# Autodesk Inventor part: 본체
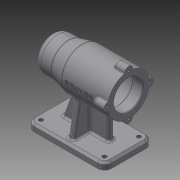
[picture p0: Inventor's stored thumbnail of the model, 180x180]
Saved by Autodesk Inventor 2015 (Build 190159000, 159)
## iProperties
Created: 2019-07
Part Number: 본체
Material: 일반
Document SubType Name: Modeling
Designer: now060
Density: 1 g/cm^3
Appearance: 기본값
Author: now060
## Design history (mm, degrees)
sketch "스케치1"
  geometry: L1 (-56, -35)-(56, -35); L2 (56, -35)-(56, 35); L3 (56, 35)-(-56, 35); L4 (-56, 35)-(-56, -35); L5 (-56, -35)-(56, 35); L6 (56, -35)-(-56, 35); 1 further point
  constraints: 12 end point, 2 midpoint, 2 parallel, 1 horizontal, 1 perpendicular
  dimensions: "d0" = 112 distance of L2.end L3.end; "d1" = 70 distance of L1.end L2.end
extrude "돌출1" new body sketch "스케치1" distance "d2" = 10; taper "d3" = 0 deg
sketch "스케치2"
  geometry: L1 (56, -35)-(56, 35) reference; L2 (-56, 35)-(-56, -35) reference; L3 (-36, 4)-(31, 4); L4 (31, 4)-(31, -4); L5 (31, -4)-(-36, -4); L6 (-36, -4)-(-36, 4); 1 further point
  constraints: 8 end point, 2 parallel, 1 horizontal, 1 perpendicular
  dimensions: "d4" = 25 distance between parallel lines of L1 L4; "d5" = 20 distance between parallel lines of L6 L2; "d6" = 4 distance from line of L3 point (0, 0); "d7" = 8 distance between parallel lines of L5 L3
extrude "돌출2" join sketch "스케치2" distance "d8" = 70; taper "d9" = 0 deg
sketch "스케치3"
  geometry: L1 (56, 35)-(-56, 35) reference; L2 (4, -28)-(-4, -28); L3 (-4, -28)-(-4, 28); L4 (-4, 28)-(4, 28); L5 (4, 28)-(4, -28); L6 (4, -28)-(-4, 28); L7 (-4, -28)-(4, 28); 1 further point
  constraints: 12 end point, 2 midpoint, 2 parallel, 1 horizontal, 1 perpendicular
  dimensions: "d10" = 8 distance between parallel lines of L5 L3; "d11" = 7 distance between parallel lines of L1 L4
extrude "돌출3" join sketch "스케치3" distance "d12" = 70; taper "d13" = 0 deg
feature "면 기울기1" dims angle "d14" = 10 deg
feature "면 기울기2" dims angle "d15" = 20 deg
sketch "스케치4"
  geometry: L1 (-56, 0)-(-56, 10) reference; L2 (-56, 10)-(-31, 10) reference; L3 (-31, 10)-(-31, 80) reference; L4 (-31, 80)-(10.522, 80) reference; L5 (10.522, 80)-(36, 10) reference; L6 (36, 10)-(56, 10) reference; L7 (56, 10)-(56, 0) reference; L8 (56, 0)-(-56, 0) reference; L9 (56, 80)-(-56, 80); L10 (-56, 80)-(-56, 110); L11 (-56, 110)-(11, 110); L12 (11, 110)-(31, 105); L13 (31, 105)-(56, 105); L14 (56, 105)-(56, 80); 1 further point
  constraints: 12 end point, 3 perpendicular, 1 collinear, 1 horizontal, 1 parallel
  dimensions: "d16" = 25 distance of L13.end L9.start; "d17" = 30 vertical distance of L9.start L11.end; "d18" = 25 distance from line of L12.end L14; "d19" = 45 distance from line of L11.end L14; "d20" = 112 distance between parallel lines of L10 L14; "d21" = 0 distance between parallel lines of L1 L10
revolve "회전1" sketch "스케치4" stored, may be unused: angle "d22" = 90 deg
fillet "모깎기1" dims "d23" = 10
sketch "스케치5"
  geometry: C1 r 6 at (-30, 0); 2 further points
  constraints: 2 horizontal alignment, 1 centre point, 1 other
  dimensions: "d24" = 6 radius of C1
extrude "돌출4" join sketch "스케치5" distance "d25" = 16; taper "d26" = 0 deg
sketch "스케치6"
  geometry: A1 r 6 centre (60, 0) between (59.4, -5.97) and (59.4, 5.97) reference; A2 r 6 centre (30, 30) between (35.97, 29.4) and (24.03, 29.4) reference; A3 r 6 centre (0, 0) between (0.6, 5.97) and (0.6, -5.97) reference; A4 r 6 centre (30, -30) between (24.03, -29.4) and (35.97, -29.4) reference; 1 further point
hole "구멍1" sketch "스케치6" at (0, 0), (30, -30), (60, 0), (30, 30) diameter "d30" = 3.242; stored, may be unused: countersink angle "d34" = 90 deg, drill point angle "d36" = 118 deg; dims "d31" = 8, "d32" = 4, "d33" = 2, "d35" = 11
sketch "스케치7"
  geometry: A1 r 30 centre (30, 0) between (35.97, -29.4) and (59.4, -5.97) reference; 1 further point
hole "구멍2" sketch "스케치7" at (30, 0) diameter "d37" = 42; stored, may be unused: countersink angle "d41" = 90 deg, drill point angle "d43" = 0 deg; dims "d38" = 8, "d39" = 4, "d40" = 2, "d42" = 15
sketch "스케치8"
  geometry: C1 r 21 at (0, 0) reference; 1 further point
hole "구멍3" sketch "스케치8" at (0, 0) diameter "d44" = 48; stored, may be unused: countersink angle "d48" = 90 deg, drill point angle "d50" = 0 deg; dims "d45" = 8, "d46" = 4, "d47" = 2, "d49" = 54
sketch "스케치9"
  geometry: C1 r 24 at (0, 0) reference; 1 further point
hole "구멍4" sketch "스케치9" at (0, 0) diameter "d51" = 42; stored, may be unused: countersink angle "d55" = 90 deg, drill point angle "d57" = 0 deg; dims "d52" = 8, "d53" = 4, "d54" = 2, "d56" = 12
sketch "스케치10"
  geometry: C1 r 21 at (0, 0) reference; 1 further point
hole "구멍5" sketch "스케치10" at (0, 0) diameter "d58" = 35; stored, may be unused: countersink angle "d62" = 90 deg, drill point angle "d64" = 0 deg; dims "d59" = 8, "d60" = 4, "d61" = 2, "d63" = 18
sketch "스케치11"
  geometry: C1 r 17.5 at (0, 0) reference; 1 further point
hole "구멍6" sketch "스케치11" at (0, 0) diameter "d65" = 32; stored, may be unused: countersink angle "d69" = 90 deg, drill point angle "d71" = 0 deg; dims "d66" = 8, "d67" = 4, "d68" = 2, "d70" = 4
sketch "스케치12"
  geometry: C1 r 16 at (0, 0) reference; 1 further point
hole "구멍7" sketch "스케치12" at (0, 0) diameter "d72" = 21; stored, may be unused: countersink angle "d76" = 90 deg, drill point angle "d78" = 0 deg; dims "d73" = 8, "d74" = 4, "d75" = 2, "d77" = 3
fillet "모깎기2" dims "d79" = 3
fillet "모깎기3" dims "d80" = 0.3
fillet "모깎기4" dims "d81" = 3
chamfer "모따기1" distance "d82" = 1; stored, may be unused: second distance "d83" = 2, angle "d84" = 45 deg
fillet "모깎기5" dims "d85" = 3
fillet "모깎기6" dims "d86" = 1
fillet "모깎기7" dims "d87" = 10
fillet "모깎기8" dims "d88" = 3
fillet "모깎기9" dims "d89" = 3
fillet "모깎기10" dims "d90" = 3
chamfer "모따기2" distance "d91" = 3; stored, may be unused: second distance "d92" = 2, angle "d93" = 45 deg
sketch "스케치13"
  geometry: A1 r 7 centre (46, -25) between (46, -32) and (53, -25) reference; A2 r 7 centre (46, 25) between (53, 25) and (46, 32) reference; A3 r 7 centre (-46, 25) between (-46, 32) and (-53, 25) reference; A4 r 7 centre (-46, -25) between (-53, -25) and (-46, -32) reference; 1 further point
hole "구멍8" sketch "스케치13" at (-46, -25), (46, -25), (46, 25), (-46, 25) diameter "d94" = 6; stored, may be unused: countersink angle "d98" = 90 deg, drill point angle "d100" = 0 deg; dims "d95" = 8, "d96" = 4, "d97" = 2, "d99" = 3
node "작업 평면1"
sketch "스케치14"
  geometry: L1 (56, 109.226)-(56, 86.771) reference; L2 (56, 85.998)-(56, 74.002) reference; L3 (56, 81.621)-(56, 78.379) reference; 3 further points
  constraints: 1 horizontal alignment, 1 midpoint, 1 other
  dimensions: "d102" = 42 distance from line of L1 point (14, 80)
feature "엠보싱1" sketch "스케치14" dims "d103" = 0.5, "d104" = 0
fillet "모깎기11" dims "d105" = 3
node "솔리드1"
pattern_circular "원형 패턴1" dims angle "d28" = 360 deg
node "절단 모서리 투영1"
